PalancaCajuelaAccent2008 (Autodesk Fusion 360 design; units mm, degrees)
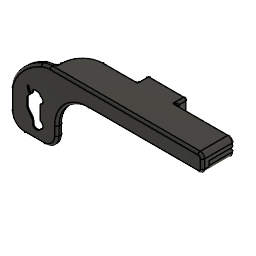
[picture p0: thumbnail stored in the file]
canvas "Canvas1"
sketch "Sketch1" plane through (0, 0, 0) normal (0, 1, 0) x axis (1, 0, 0)
  line L1 (-10, -18) -> (-22, -18)
  line L2 (-10, 8) -> (-10, 4)
  line L3 (-25, 14) -> (-16, 14)
  line L4 (-31, -9) -> (-31, 8)
  line L5 (29, -18) -> (-10, -18)
  line L6 (31, -12) -> (31, -16)
  line L7 (4, -10) -> (29, -10)
  arc A1 centre (4, 4) radius 14 clockwise from (4, -10) to (-10, 4)
  arc A2 centre (-22, -9) radius 9 clockwise from (-22, -18) to (-31, -9)
  arc A3 centre (-25, 8) radius 6 clockwise from (-31, 8) to (-25, 14)
  arc A4 centre (-16, 8) radius 6 clockwise from (-16, 14) to (-10, 8)
  arc A5 centre (29, -12) radius 2 clockwise from (29, -10) to (31, -12)
  arc A6 centre (29, -16) radius 2 clockwise from (31, -16) to (29, -18)
  horizontal L1
  vertical L2
  horizontal L3
  vertical L4
  horizontal L5
  vertical L6
  horizontal L7
  tangent L7 A1
  tangent L2 A1
  tangent L1 A2
  tangent L4 A2
  tangent L3 A3
  tangent L4 A3
  tangent L2 A4
  tangent L3 A4
  tangent L6 A5
  tangent L7 A5
  tangent L5 A6
  tangent L6 A6
  equal A5 A6
  dimension "d1" radius A1 = 14
  dimension "d2" radius A2 = 9
  dimension "d3" radius A3 = 6
  dimension "d4" radius A4 = 6
  dimension "d5" radius A5 = 2
extrude "Extrude1" new body sketch "Sketch1" along normal blind 3
canvas "Canvas2"
sketch "Sketch2" plane through (0, 0, 0) normal (1, 0, 0) x axis (0, 1, 0)
  line L1 (0, 10) -> (0, -4)
  line L2 (3, -4) -> (0, -4)
  line L3 (3, -4) -> (3, 10)
  line L4 (0, 10) -> (3, 10)
  line L5 (0, 12) -> (0, 16)
  line L6 (3, 12) -> (0, 12)
  line L7 (3, 16) -> (3, 12)
  line L8 (0, 16) -> (3, 16)
  line L9 (0, 12) -> (0, 10)
  line L10 (3, 10) -> (0, 10)
  line L11 (3, 12) -> (3, 10)
  line L12 (0, 12) -> (3, 12)
  line L13 (0, 18) -> (0, 16)
  line L14 (3, 16) -> (0, 16)
  line L15 (3, 18) -> (3, 16)
  line L16 (0, 18) -> (3, 18)
  line L17 (0, -8) -> (0, -4)
  line L18 (3, -8) -> (0, -8)
  line L19 (3, -4) -> (3, -8)
  line L20 (0, -4) -> (3, -4)
  line L21 (0, -8) -> (0, -14)
  line L22 (3, -14) -> (0, -14)
  line L23 (3, -8) -> (3, -14)
  line L24 (0, -8) -> (3, -8)
  line L25 (18.5, 10) -> (3, 10)
  line L26 (18.5, 18) -> (18.5, 10)
  line L27 (3, 18) -> (18.5, 18)
  line L28 (3, 10) -> (3, 18)
  line L29 (3, 18) -> (15.1, 18)
  line L30 (3, 10) -> (3, 18)
  line L31 (15.1, 10) -> (3, 10)
  line L32 (15.1, 18) -> (15.1, 10)
  point P12 (3, 10)
  point P26 (3, 10)
  point P5 (3, 10)
  point P32 (3, 10)
  point P30 (15.1, 18)
  horizontal L25
  vertical L26
  horizontal L27
  vertical L28
  coincident P12 P26
  horizontal L29
  vertical L30
  horizontal L31
  vertical L32
  coincident P5 P32
  coincident L27 P30
extrude "Extrude2" add sketch "Sketch2" profile of L7 L11 L15 L25 L26 L27 L28 L29 L30 L31 L32 along normal blind 31 and against normal blind 12.915
sketch "Sketch3" plane through (31, 0, 0) normal (1, 0, 0) x axis (0, 1, 0)
  line L1 (0, 12) -> (0, 16)
  line L2 (3, 12) -> (0, 12)
  line L3 (3, 10) -> (3, 12)
  line L4 (18.5, 10) -> (3, 10)
  line L5 (18.5, 18) -> (18.5, 10)
  line L6 (3, 18) -> (18.5, 18)
  line L7 (3, 16) -> (3, 18)
  line L8 (0, 16) -> (3, 16)
  line L9 (0, 12) -> (0, 10)
  line L10 (3, 10) -> (0, 10)
  line L11 (3, 12) -> (3, 10)
  line L12 (0, 12) -> (3, 12)
  line L13 (17, 12) -> (3, 12)
  line L14 (17, 14.3) -> (17, 12)
  line L15 (3, 14.3) -> (17, 14.3)
  line L16 (3, 12) -> (3, 14.3)
  point P13 (3, 12)
  point P14 (3, 12)
  point P17 (3, 14.3)
  horizontal L13
  vertical L14
  horizontal L15
  vertical L16
  coincident P13 P14
  dimension "d12" distance P14 P17 = 2.3
extrude "Extrude3" cut sketch "Sketch3" profile of L13 L14 L15 L16 against normal blind 43.915
sketch "Sketch4" plane through (0, 18.5, 0) normal (0, 1, 0) x axis (-1, 0, 0)
  line L1 (-31, 18) -> (12.915, 18)
  line L2 (-31, 10) -> (-31, 18)
  line L3 (12.915, 10) -> (-31, 10)
  line L4 (12.915, 18) -> (12.915, 10)
  line L5 (-5, 18) -> (-31, 18)
  line L6 (-5, 10) -> (-5, 18)
  line L7 (-31, 10) -> (-5, 10)
  line L8 (-31, 18) -> (-31, 10)
  point P8 (-5, 10)
  point P3 (-31, 18)
  point P6 (-31, 18)
  horizontal L5
  vertical L6
  horizontal L7
  vertical L8
  coincident L3 P8
  coincident P3 P6
extrude "Extrude4" cut sketch "Sketch4" profile of L1 L2 L3 L5 L6 L7 L8 against normal blind 4
offset_faces "OffsetFaces1" distance 1
work_plane "WorkPlane1" AlongDistance 0
split "Split1"
move "Move1"
extrude "Extrude6" add of existing geometry blind 25
fillet "Fillet1" radius 2
sketch "Sketch6" plane through (0, 0, 0) normal (0, -1, 0) x axis (1, 0, 0)
  line L1 (-47, 18) -> (29, 18)
  line L2 (-56, -8) -> (-56, 9)
  line L3 (-41, -14) -> (-50, -14)
  line L4 (-35, -4) -> (-35, -8)
  line L5 (29, 10) -> (-21, 10)
  line L6 (31, 16) -> (31, 12)
  curve K1 (-56, 0.5) -> (-40, 18)
  arc A1 centre (-47, 9) radius 9 clockwise from (-56, 9) to (-47, 18)
  arc A2 centre (-50, -8) radius 6 clockwise from (-50, -14) to (-56, -8)
  arc A3 centre (-41, -8) radius 6 clockwise from (-35, -8) to (-41, -14)
  arc A4 centre (-21, -4) radius 14 clockwise from (-35, -4) to (-21, 10)
  arc A5 centre (29, 12) radius 2 clockwise from (31, 12) to (29, 10)
  arc A6 centre (29, 16) radius 2 clockwise from (29, 18) to (31, 16)
  point P20 (-40, 18)
  point P23 (-56, 0.5)
  coincident L1 P20
  midpoint L2 P23
extrude "Extrude7" cut sketch "Sketch6" profile of L1 A1 L2 K1 against normal blind 3
fillet "Fillet5" radius 10
fillet "Fillet6" radius 1
extrude "Extrude9" add of existing geometry blind 25
offset_faces "OffsetFaces2" distance 0.4
sketch "Sketch7" plane through (0, 0, 0) normal (0, -1, 0) x axis (1, 0, 0)
  curve K1 (-41.7085, 16.2399) -> (-55, 1.1219)
  line L1 (-55, -8) -> (-55, 1.1219)
  line L2 (-41, -13) -> (-50, -13)
  line L3 (-36, -4) -> (-36, -8)
  line L4 (29, 11) -> (-21, 11)
  line L5 (30, 16) -> (30, 12)
  line L6 (-38.0885, 17) -> (29, 17)
  curve K2 (-38.0885, 17) -> (-41.7085, 16.2399)
  line L7 (-38.0585, -11.5326) -> (-45.3317, -11.5326)
  line L8 (-38.0585, -1.835) -> (-38.0585, -11.5326)
  line L9 (-38.0585, 7.8627) -> (-38.0585, -1.835)
  line L10 (-45.3317, 7.8627) -> (-38.0585, 7.8627)
  line L11 (-52.605, 7.8627) -> (-45.3317, 7.8627)
  line L12 (-52.605, -1.835) -> (-52.605, 7.8627)
  line L13 (-52.605, -11.5326) -> (-52.605, -1.835)
  line L14 (-45.3317, -11.5326) -> (-52.605, -11.5326)
  curve K3 (-48.1747, 1.8243) -> (-48.5626, 0.8367)
  curve K4 (-47.7497, 2.2526) -> (-48.1747, 1.8243)
  curve K5 (-47.3698, 2.6033) -> (-47.7497, 2.2526)
  line L15 (-47.2809, 2.6858) -> (-47.3698, 2.6033)
  line L16 (-47.3133, 2.7262) -> (-47.2809, 2.6858)
  curve K6 (-47.8353, 3.5295) -> (-47.3133, 2.7262)
  curve K7 (-48.3784, 5.3656) -> (-47.8353, 3.5295)
  curve K8 (-48.2976, 5.8391) -> (-48.3784, 5.3656)
  curve K9 (-47.8402, 5.9393) -> (-48.2976, 5.8391)
  curve K10 (-47.6252, 5.7325) -> (-47.8402, 5.9393)
  curve K11 (-47.5379, 5.3058) -> (-47.6252, 5.7325)
  curve K12 (-46.7896, 3.3808) -> (-47.5379, 5.3058)
  line L17 (-46.6829, 3.2385) -> (-46.7896, 3.3808)
  line L18 (-46.6037, 3.3161) -> (-46.6829, 3.2385)
  curve K13 (-46.1867, 3.8301) -> (-46.6037, 3.3161)
  line L19 (-46.1075, 3.9578) -> (-46.1867, 3.8301)
  line L20 (-46.1075, 4.2907) -> (-46.1075, 3.9578)
  curve K14 (-46.0025, 4.9453) -> (-46.1075, 4.2907)
  curve K15 (-45.5014, 5.4383) -> (-46.0025, 4.9453)
  curve K16 (-44.3377, 5.5434) -> (-45.5014, 5.4383)
  curve K17 (-43.1659, 5.4254) -> (-44.3377, 5.5434)
  curve K18 (-42.9073, 5.2282) -> (-43.1659, 5.4254)
  curve K19 (-42.5937, 4.6011) -> (-42.9073, 5.2282)
  line L21 (-42.5759, 4.4831) -> (-42.5937, 4.6011)
  line L22 (-42.458, 4.4427) -> (-42.5759, 4.4831)
  curve K20 (-41.291, 3.0737) -> (-42.458, 4.4427)
  curve K21 (-41.3217, 2.3819) -> (-41.291, 3.0737)
  curve K22 (-42.0426, 1.3717) -> (-41.3217, 2.3819)
  curve K23 (-42.5081, 1.1552) -> (-42.0426, 1.3717)
  line L23 (-42.584, 1.1358) -> (-42.5081, 1.1552)
  line L24 (-42.584, -2.0936) -> (-42.584, 1.1358)
  line L25 (-42.584, -5.3229) -> (-42.584, -2.0936)
  line L26 (-42.5081, -5.3423) -> (-42.584, -5.3229)
  curve K24 (-42.0426, -5.5589) -> (-42.5081, -5.3423)
  curve K25 (-41.3217, -6.5674) -> (-42.0426, -5.5589)
  curve K26 (-41.2975, -7.3044) -> (-41.3217, -6.5674)
  curve K27 (-42.5, -8.6395) -> (-41.2975, -7.3044)
  line L27 (-42.6277, -8.6767) -> (-42.5, -8.6395)
  line L28 (-42.6551, -8.7639) -> (-42.6277, -8.6767)
  curve K28 (-43.3033, -9.5042) -> (-42.6551, -8.7639)
  curve K29 (-44.2488, -9.6335) -> (-43.3033, -9.5042)
  curve K30 (-44.96, -9.5963) -> (-44.2488, -9.6335)
  curve K31 (-45.8408, -8.7365) -> (-44.96, -9.5963)
  curve K32 (-45.899, -8.1869) -> (-45.8408, -8.7365)
  curve K33 (-46.2869, -6.0696) -> (-45.899, -8.1869)
  curve K34 (-47.2486, -4.8008) -> (-46.2869, -6.0696)
  curve K35 (-48.2895, -3.427) -> (-47.2486, -4.8008)
  curve K36 (-48.5626, -2.6657) -> (-48.2895, -3.427)
  curve K37 (-48.5626, 0.8367) -> (-48.5626, -2.6657)
  curve K38 (-47.4555, -3.2201) -> (-47.748, -2.5704)
  curve K39 (-46.3758, -4.5907) -> (-47.4555, -3.2201)
  curve K40 (-45.5822, -5.6736) -> (-46.3758, -4.5907)
  curve K41 (-45.0957, -8.09) -> (-45.5822, -5.6736)
  curve K42 (-44.9438, -8.6912) -> (-45.0957, -8.09)
  curve K43 (-44.2052, -8.8302) -> (-44.9438, -8.6912)
  line L29 (-43.7397, -8.8254) -> (-44.2052, -8.8302)
  line L30 (-43.6572, -8.7817) -> (-43.7397, -8.8254)
  curve K44 (-43.4342, -8.5441) -> (-43.6572, -8.7817)
  curve K45 (-43.3954, -8.1514) -> (-43.4342, -8.5441)
  line L31 (-43.3889, -7.8313) -> (-43.3954, -8.1514)
  line L32 (-43.1352, -7.8313) -> (-43.3889, -7.8313)
  curve K46 (-42.7861, -7.8071) -> (-43.1352, -7.8313)
  curve K47 (-42.1606, -7.1073) -> (-42.7861, -7.8071)
  curve K48 (-42.3965, -6.4026) -> (-42.1606, -7.1073)
  curve K49 (-43.1465, -6.1504) -> (-42.3965, -6.4026)
  line L33 (-43.3922, -6.1504) -> (-43.1465, -6.1504)
  line L34 (-43.3922, -2.0952) -> (-43.3922, -6.1504)
  line L35 (-43.3922, 1.9601) -> (-43.3922, -2.0952)
  line L36 (-43.1061, 1.9665) -> (-43.3922, 1.9601)
  curve K50 (-42.7117, 2.0166) -> (-43.1061, 1.9665)
  curve K51 (-42.2866, 2.3544) -> (-42.7117, 2.0166)
  curve K52 (-42.4127, 3.4131) -> (-42.2866, 2.3544)
  curve K53 (-43.1303, 3.6442) -> (-42.4127, 3.4131)
  line L37 (-43.3922, 3.6442) -> (-43.1303, 3.6442)
  line L38 (-43.3922, 4.0855) -> (-43.3922, 3.6442)
  curve K54 (-43.4293, 4.5978) -> (-43.3922, 4.0855)
  curve K55 (-43.5215, 4.7029) -> (-43.4293, 4.5978)
  curve K56 (-44.3458, 4.7352) -> (-43.5215, 4.7029)
  curve K57 (-45.1701, 4.7013) -> (-44.3458, 4.7352)
  curve K58 (-45.2622, 4.614) -> (-45.1701, 4.7013)
  curve K59 (-45.2994, 4.2277) -> (-45.2622, 4.614)
  curve K60 (-45.4109, 3.5634) -> (-45.2994, 4.2277)
  curve K61 (-46.7459, 2.0781) -> (-45.4109, 3.5634)
  curve K62 (-47.6478, 1.1859) -> (-46.7459, 2.0781)
  curve K63 (-47.727, 0.9838) -> (-47.6478, 1.1859)
  line L39 (-47.7642, 0.8561) -> (-47.727, 0.9838)
  line L40 (-47.7674, -0.8086) -> (-47.7642, 0.8561)
  curve K64 (-47.748, -2.5704) -> (-47.7674, -0.8086)
  arc A1 centre (-50, -8) radius 5 clockwise from (-50, -13) to (-55, -8)
  arc A2 centre (-41, -8) radius 5 clockwise from (-36, -8) to (-41, -13)
  arc A3 centre (-21, -4) radius 15 clockwise from (-36, -4) to (-21, 11)
  arc A4 centre (29, 12) radius 1 clockwise from (30, 12) to (29, 11)
  arc A5 centre (29, 16) radius 1 clockwise from (29, 17) to (30, 16)
extrude "Extrude8" cut sketch "Sketch7" profile of K3 K4 K5 L15 L16 K6 K7 K8 K9 K10 K11 K12 L17 L18 K13 L19 L20 K14 K15 K16 K17 K18 K19 L21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 against normal blind 0.5
sketch "Sketch8" plane through (-37.915, 0, 0) normal (-1, 0, 0) x axis (0, -1, 0)
  line L1 (-3, 14.3) -> (-17, 14.3)
  line L2 (-3, 17) -> (-3, 14.3)
  line L3 (-19.5, 18) -> (-2, 18)
  line L4 (-19.5, 10) -> (-19.5, 18)
  line L5 (-3, 10) -> (-19.5, 10)
  line L6 (-3, 12.4) -> (-3, 10)
  line L7 (-17, 12.4) -> (-3, 12.4)
  line L8 (-17, 14.3) -> (-17, 12.4)
  line L9 (-14.5, 14.3) -> (-14.5, 18)
  line L10 (-17, 14.3) -> (-14.5, 14.3)
  line L11 (-17, 12.4) -> (-17, 14.3)
  line L12 (-14.5, 12.4) -> (-17, 12.4)
  line L13 (-14.5, 10) -> (-14.5, 12.4)
  line L14 (-19.5, 10) -> (-14.5, 10)
  line L15 (-19.5, 18) -> (-19.5, 10)
  line L16 (-14.5, 18) -> (-19.5, 18)
  arc A1 centre (-2, 17) radius 1 clockwise from (-3, 17) to (-2, 18)
extrude "Extrude10" cut sketch "Sketch8" profile of L1 L3 L4 L5 L7 L8 L9 L10 L11 L12 L13 L14 L15 L16 against normal blind 25
fillet "Fillet10" radius 1
fillet "Fillet11" radius 1
fillet "Fillet12" radius 10
fillet "Fillet13" radius 1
